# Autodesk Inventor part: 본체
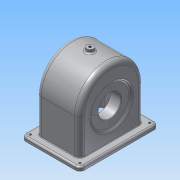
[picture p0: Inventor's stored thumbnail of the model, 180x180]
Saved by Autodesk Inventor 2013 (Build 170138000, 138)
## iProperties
Created: 2016-01
Part Number: 본체
Material: 알루미늄 6061
Document SubType Name: Modeling
Designer: Administrator
Density: 2.71 g/cm^3
Mass: 912.387 g
Surface Area: 1058.7 cm^2
Volume: 336.674 cm^3
Author: Administrator
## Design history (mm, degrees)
sketch "스케치1"
  geometry: L1 (-44, 70)-(44, 70); L2 (52, 62)-(52, -62); L3 (44, -70)-(-44, -70); L4 (-52, -62)-(-52, 62); A1 r 8 centre (-44, 62) between (-44, 70) and (-52, 62); A2 r 8 centre (-44, -62) between (-52, -62) and (-44, -70); A3 r 8 centre (44, -62) between (44, -70) and (52, -62); A4 r 8 centre (44, 62) between (52, 62) and (44, 70); 3 further points
  constraints: 8 end point, 8 point on circle, 8 tangent, 4 centre point, 3 equal radius, 2 midpoint, 2 parallel, 1 horizontal, 1 horizontal alignment, 1 perpendicular, 1 vertical alignment
  dimensions: "d0" = 140 distance between parallel lines of L3 L1; "d2" = 104 distance between parallel lines of L2 L4; "d3" = 8 radius of A1
extrude "돌출1" new body sketch "스케치1" distance "d4" = 7; taper "d5" = 0 deg
sketch "스케치2"
  geometry: L1 (-62, 0)-(62, 0) reference; L2 (-70, 0)-(-70, 7) reference; L3 (70, 0)-(70, 7) reference; L4 (62, 7)-(-62, 7) reference; L5 (-57, 70)-(-57, 7); L6 (57, 70)-(57, 7); A1 r 57 centre (0, 70) between (57, 70) and (-57, 70); 2 further points
  constraints: 4 end point, 2 perpendicular, 2 point on circle, 2 point on line, 2 tangent, 1 centre point, 1 midpoint, 1 vertical alignment
  dimensions: "d6" = 114 diameter of A1; "d10" = 127 dimension on A1 L1
extrude "돌출2" join sketch "스케치2" stored distance "d11" = 77; taper "d12" = 0 deg
node "작업 평면3"
  node "작업 평면2"
sketch "스케치3"
  geometry: L1 (57, 70)-(57, 7) reference; L2 (-57, 7)-(57, 7) reference; L3 (-57, 7)-(-57, 70) reference; L4 (51, 70)-(51, 0); L5 (-51, 0)-(-51, 70); L6 (-62, 0)-(62, 0) reference; A1 r 57 centre (0, 70) between (57, 70) and (-57, 70) reference; A2 r 51 centre (0, 70) between (51, 70) and (-51, 70); 1 further point
  constraints: 4 end point, 2 point on circle, 2 point on line, 1 centre point, 1 other
  dimensions: "d16" = 6 distance between parallel lines of L5 L3; "d17" = 51 radius of A2
extrude "돌출3" cut sketch "스케치3" distance "d18" = 67; taper "d19" = 0 deg
sketch "스케치4"
  geometry: L1 (33.5, 0)-(-33.5, 0) reference; L2 (-38.5, 70)-(-38.5, 7) reference; L3 (38.5, 7)-(38.5, 70) reference; L4 (38.5, 70)-(38.5, 127) reference; L5 (-52.804, 60)-(49.974, 60); L6 (-33.5, 70)-(-33.5, 121) reference; L7 (-33.5, 0)-(-33.5, 70) reference; L8 (-35.5, 94.899)-(-35.5, 60); L9 (-33.5, 99.747)-(-19.5, 88); L10 (-19.5, 88)-(-19.5, 60); L11 (-35.5, 60)-(-19.5, 60); L12 (-35.5, 94.899)-(-41.279, 99.747); L13 (-33.5, 99.747)-(-41.279, 99.747); L14 (-38.5, 127)-(-38.5, 70) reference; 1 further point
  constraints: 14 end point, 3 perpendicular, 3 point on line, 2 parallel, 1 collinear
  dimensions: "d20" = 60 distance between parallel lines of L1 L5; "d21" = 5 distance between parallel lines of L9 L12; "d22" = 16 distance between parallel lines of L10 L8; "d23" = 56 diameter of L9.end L5; "d24" = 3 distance between parallel lines of L8 L14; "d25" = 50 deg angle of L10 L9
revolve "회전1" sketch "스케치4" stored, may be unused: angle "d26" = 90 deg
sketch "스케치5"
  geometry: C1 r 31 at (60, 0); A1 r 57 centre (70, 0) between (70, -57) and (70, 57) reference; 1 further point
  constraints: 1 centre point, 1 horizontal alignment
  dimensions: "d27" = 62 diameter of C1; "d29" = 60 distance of C1.centre point (0, 0)
extrude "돌출4" join sketch "스케치5" distance "d30" = 10; taper "d31" = 0 deg
hole "구멍1" diameter "d34" = 40; stored, may be unused: countersink angle "d38" = 90 deg, drill point angle "d40" = 118 deg; dims "d32" = 10, "d33" = 10, "d35" = 6, "d36" = 4, "d37" = 2, "d39" = 8
sketch "스케치6" dims "d41" = 56
  geometry: C1 r 20 at (0, 0) reference; 3 further points
  constraints: 2 horizontal alignment, 1 coincident, 2 other
hole "구멍2" sketch "스케치6" at (-28, 0) diameter "d43" = 2.459; stored, may be unused: countersink angle "d47" = 90 deg, drill point angle "d49" = 118 deg; dims "d44" = 7, "d45" = 4, "d46" = 2, "d48" = 9
sketch "스케치7" dims "d53" = 48
  geometry: C1 r 20 at (0, 0) reference; 3 further points
  constraints: 2 horizontal alignment, 1 coincident, 2 other
hole "구멍3" sketch "스케치7" at (24, 0) diameter "d55" = 2.459; stored, may be unused: countersink angle "d59" = 90 deg, drill point angle "d61" = 118 deg; dims "d56" = 6, "d57" = 4, "d58" = 2, "d60" = 8
node "작업 평면5"
  node "작업 평면4"
sketch "스케치8"
  geometry: C1 r 6 at (38.5, 0); 1 further point
  constraints: 1 centre point, 1 coincident
  dimensions: "d66" = 12 diameter of C1
extrude "돌출5" join sketch "스케치8" distance "d68" = 10; taper "d69" = 0 deg
hole "구멍4" diameter "d72" = 4.459; stored, may be unused: countersink angle "d76" = 90 deg, drill point angle "d78" = 118 deg; dims "d70" = 10, "d71" = 10, "d73" = 30, "d74" = 4, "d75" = 2, "d77" = 8
fillet "모깎기1" dims "d79" = 3
hole "구멍5" diameter "d82" = 4; stored, may be unused: countersink angle "d86" = 90 deg, drill point angle "d88" = 118 deg; dims "d80" = 10, "d81" = 10, "d83" = 8, "d84" = 4, "d85" = 2, "d87" = 8
hole "구멍6" diameter "d91" = 4; stored, may be unused: countersink angle "d95" = 90 deg, drill point angle "d97" = 118 deg; dims "d89" = 10, "d90" = 10, "d92" = 8, "d93" = 4, "d94" = 2, "d96" = 8
hole "구멍7" diameter "d100" = 4; stored, may be unused: countersink angle "d104" = 90 deg, drill point angle "d106" = 118 deg; dims "d98" = 10, "d99" = 10, "d101" = 8, "d102" = 4, "d103" = 2, "d105" = 8
hole "구멍8" diameter "d109" = 4; stored, may be unused: countersink angle "d113" = 90 deg, drill point angle "d115" = 118 deg; dims "d107" = 10, "d108" = 10, "d110" = 8, "d111" = 4, "d112" = 2, "d114" = 8
fillet "모깎기2" dims "d116" = 9
fillet "모깎기3" dims "d117" = 9
fillet "모깎기4" dims "d118" = 3
feature "면 이동1"
feature "면 이동2"
feature "면 이동3" dims "d119" = 3
sketch "스케치9"
  geometry: L1 (-112.375, 55.631)-(-12.239, 55.631); L2 (-12.239, 55.631)-(-12.239, -42.465); L3 (-12.239, -42.465)-(-112.375, -42.465); L4 (-112.375, -42.465)-(-112.375, 55.631); 1 further point
  constraints: 8 end point, 2 parallel, 1 horizontal, 1 perpendicular
extrude "돌출6" cut sketch "스케치9" distance "d120" = 10; taper "d121" = 0 deg
fillet "모깎기5" dims "d122" = 3
fillet "모깎기6" dims "d123" = 1
fillet "모깎기7" dims "d124" = 3
chamfer "모따기1" distance "d125" = 1; stored, may be unused: second distance "d126" = 2, angle "d127" = 45 deg
chamfer "모따기2" distance "d128" = 1; stored, may be unused: second distance "d129" = 2, angle "d130" = 45 deg
fillet "모깎기8" dims "d131" = 3
sketch "스케치10"
  geometry: L1 (54.387, 23.094)-(4.613, 23.094); L2 (4.613, 23.094)-(4.613, 56.906); L3 (4.613, 56.906)-(54.387, 56.906); L4 (54.387, 56.906)-(54.387, 23.094); L5 (-14.5, 70)-(73.5, 70) reference; 5 further points
  constraints: 3 midpoint, 2 vertical alignment, 1 horizontal alignment, 2 other
  dimensions: "d132" = 30 distance from line of L5 point (29.5, 40)
feature "엠보싱1" sketch "스케치10" dims "d0" = 140, "d2" = 104, "d3" = 8, "d133" = 0.5, "d134" = 0
node "솔리드1"
pattern_circular "원형 패턴1" dims angle "d51" = 360 deg
pattern_circular "원형 패턴2" dims angle "d63" = 360 deg
node "작업 평면1"
node "투영된 루프1"
other parameters: "d13" = 38.5, "d14" = -6, "d15" = 1, "d65" = 6
